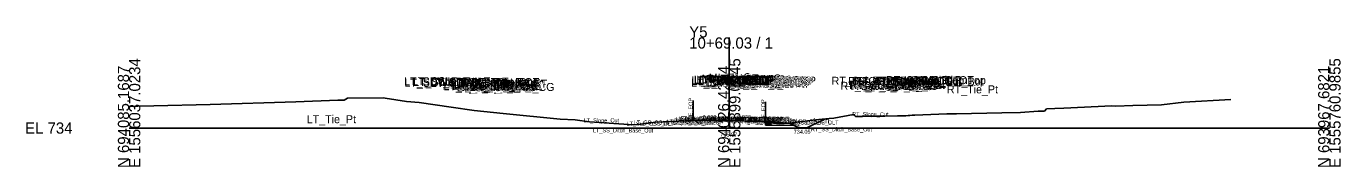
# Model space of a CAD drawing. Extents: x -26 to 4229, y -10 to 9523.
# Drawn here: x -25.7 to 302.8, y 490.3 to 525.5 of the extents above; entities that cross this region are included whole.
import ezdxf

# ---------------------------------------------------------------- set-up
doc = ezdxf.new("R2010")
doc.units = 0
for name, color, linetype in [('Default', 7, 'Continuous'), ('Exist Cross Section Cell', 7, 'Continuous'), ('Exist XS Center Line Elevation Label', 7, 'Continuous'), ('Exist XS Ground Line', 7, 'Continuous'), ('Prop CMT Pvmt Course 1', 7, 'Continuous'), ('Prop CMT Pvmt Course 2', 7, 'Continuous'), ('Prop CMT Pvmt Course 3', 7, 'Continuous'), ('Prop CMT Pvmt Surface', 7, 'Continuous'), ('Prop CMT Pvmt Surface Shoulder', 7, 'Continuous'), ('Prop CMT Pvmt Wedge Surface 1', 7, 'Continuous'), ('Prop CMT Pvmt Wedge Surface 2', 7, 'Continuous'), ('Prop CMT Pvmt Wedge Surface 3', 7, 'Continuous'), ('Prop CMT Shld Paved Course 1', 7, 'Continuous'), ('Prop CMT Shld Paved Course 2', 7, 'Continuous'), ('Prop CMT Shld Paved Course 3', 7, 'Continuous'), ('Prop CMT Slope Grass', 7, 'Continuous'), ('Prop CMT Subgrade Earthwork', 7, 'Continuous'), ('Prop XS Earthwork Shape', 7, 'Continuous'), ('Prop XS Label Text', 7, 'Continuous'), ('Prop XSC Text', 7, 'Continuous'), ('Scratch_Level_1', 7, 'Continuous')]:
    doc.layers.add(name, color=color, linetype=linetype)

msp = doc.modelspace()

# ---------------------------------------------------------------- linework, layer by layer
at = {"layer": 'Exist Cross Section Cell'}
for p, q in [((150, 500), (150, 522.7)), ((0, 500), (150, 500)), ((150, 500), (300, 500))]:
    msp.add_line(p, q, dxfattribs=at)
at = {"layer": 'Exist XS Ground Line'}
msp.add_lwpolyline([(0, 505.41), (2.22, 505.46), (6.16, 505.53), (20.25, 505.91), (41.67, 506.58), (52.17, 507.02), (52.65, 507.01), (53.79, 507), (54.59, 507.5), (63.56, 507.57), (64.04, 507.5), (69.31, 506.67), (72.47, 506.43), (80.52, 505.2), (86.27, 504.37), (93.54, 503.63), (107.74, 502.22), (111.52, 502.03), (115.06, 501.59), (126.06, 500.78), (127.93, 501.01), (131.58, 501.47), (140.95, 501.93), (150, 501.87), (150.54, 501.87), (151.66, 501.83), (158.35, 501.58), (159.09, 501.56), (159.44, 501.53), (159.77, 501.49), (161.09, 501.2), (162.46, 501.08), (165.03, 501.25), (170.25, 501.85), (172.44, 502.13), (174.95, 502.37), (176.18, 502.49), (181.05, 503.4), (181.59, 502.9), (182.81, 502.93), (183.2, 502.95), (188.92, 503.01), (192.05, 503.06), (194.18, 503.09), (194.69, 503.11), (195.18, 503.16), (195.73, 503.19), (196.4, 503.19), (204.41, 503.53), (205.62, 503.55), (206.78, 503.56), (218.18, 503.78), (222.84, 503.92), (227.19, 504.27), (227.92, 504.25), (228.8, 504.27), (229.34, 504.8), (231.35, 504.92), (233.63, 504.96), (245.6, 505.53), (246.63, 505.5), (250.88, 505.68), (258.05, 505.79), (263.61, 506.51), (275.35, 507.12)], dxfattribs=at)
at = {"layer": 'Prop CMT Pvmt Course 1'}
for points in [[(150, 501.89), (159.22, 501.63)], [(159.22, 501.38), (159.09, 501.38)], [(159.22, 501.63), (159.22, 501.38)]]:
    msp.add_lwpolyline(points, dxfattribs=at)
at = {"layer": 'Prop CMT Pvmt Course 2'}
for points in [[(159.09, 501.38), (159.22, 501.38)], [(159.22, 501.13), (159.09, 501.13)], [(159.22, 501.38), (159.22, 501.13)]]:
    msp.add_lwpolyline(points, dxfattribs=at)
at = {"layer": 'Prop CMT Pvmt Course 3'}
for points in [[(159.09, 501.13), (159.22, 501.13)], [(159.22, 500.75), (159.09, 500.76)], [(159.22, 501.13), (159.22, 500.75)]]:
    msp.add_lwpolyline(points, dxfattribs=at)
at = {"layer": 'Prop CMT Pvmt Surface'}
for points in [[(150, 501.89), (140.95, 501.93)], [(150, 501.89), (159.22, 501.63)]]:
    msp.add_lwpolyline(points, dxfattribs=at)
at = {"layer": 'Prop CMT Pvmt Surface Shoulder'}
for points in [[(140.68, 501.9), (140.68, 501.9)], [(159.22, 501.63), (159.22, 501.63)]]:
    msp.add_lwpolyline(points, dxfattribs=at)
at = {"layer": 'Prop CMT Pvmt Wedge Surface 1'}
for points in [[(159.09, 501.38), (159.22, 501.38)], [(159.22, 501.38), (159.22, 501.63)]]:
    msp.add_lwpolyline(points, dxfattribs=at)
at = {"layer": 'Prop CMT Pvmt Wedge Surface 2'}
msp.add_lwpolyline([(159.22, 501.38), (159.22, 501.63)], dxfattribs=at)
at = {"layer": 'Prop CMT Pvmt Wedge Surface 3'}
msp.add_lwpolyline([(159.22, 501.13), (159.22, 501.63)], dxfattribs=at)
at = {"layer": 'Prop CMT Shld Paved Course 1'}
for points in [[(140.68, 501.9), (140.68, 501.9)], [(159.22, 501.63), (159.22, 501.63)], [(159.22, 501.63), (159.47, 501.37)], [(159.22, 501.38), (159.22, 501.63)], [(159.47, 501.37), (159.22, 501.38)]]:
    msp.add_lwpolyline(points, dxfattribs=at)
at = {"layer": 'Prop CMT Shld Paved Course 2'}
for points in [[(159.22, 501.38), (159.47, 501.37), (159.73, 501.12)], [(159.22, 501.13), (159.22, 501.38)], [(159.73, 501.12), (159.22, 501.13)]]:
    msp.add_lwpolyline(points, dxfattribs=at)
at = {"layer": 'Prop CMT Shld Paved Course 3'}
for points in [[(159.22, 501.13), (159.73, 501.12), (160.23, 501.11), (160.61, 500.72)], [(159.22, 500.75), (159.22, 501.13)], [(160.61, 500.72), (159.22, 500.75)]]:
    msp.add_lwpolyline(points, dxfattribs=at)
at = {"layer": 'Prop CMT Slope Grass'}
for p, q in [((165.22, 501.15), (167.41, 500.05)), ((167.41, 500.05), (169.41, 500.05)), ((173.84, 502.26), (169.41, 500.05))]:
    msp.add_line(p, q, dxfattribs=at)
msp.add_lwpolyline([(159.22, 501.63), (165.22, 501.15)], dxfattribs=at)
at = {"layer": 'Prop CMT Subgrade Earthwork'}
for points in [[(159.09, 500.76), (159.09, 501.56)], [(159.09, 500.76), (159.22, 500.75)], [(159.22, 500.75), (160.61, 500.72)], [(160.61, 500.72), (166.29, 500.61)]]:
    msp.add_lwpolyline(points, dxfattribs=at)
at = {"layer": 'Prop XS Earthwork Shape'}
for points in [[(150.54, 501.87), (151.66, 501.83), (158.35, 501.58), (159.09, 501.56), (159.44, 501.53), (159.77, 501.49), (161.09, 501.2), (162.46, 501.08), (164.44, 501.21), (159.22, 501.63), (150, 501.89), (140.95, 501.93), (150, 501.87)], [(160.61, 500.72), (166.29, 500.61), (165.22, 501.15), (164.44, 501.21), (162.46, 501.08), (161.09, 501.2), (159.77, 501.49), (159.44, 501.53), (159.09, 501.56), (159.09, 500.76), (159.22, 500.75)], [(164.44, 501.21), (165.03, 501.25), (170.25, 501.85), (172.44, 502.13), (173.84, 502.26), (169.41, 500.05), (167.41, 500.05), (166.29, 500.61), (165.22, 501.15)]]:
    msp.add_lwpolyline(points, close=True, dxfattribs=at)
at = {"layer": 'Prop XS Label Text'}
for p, q in [((140.95, 506.93), (140.95, 501.93)), ((159.09, 506.56), (159.09, 501.56))]:
    msp.add_line(p, q, dxfattribs=at)

# ---------------------------------------------------------------- texts
at = {"layer": 'Default'}
for s, height, p in [('LT_SDWK_Out_Top', 2, (68.76, 510.71)), ('LT_CSLP_Pnt', 2, (70.7, 510.74)), ('LT_Sub_Trench_Out_DLT', 2, (71.02, 510.54)), ('LT_SDWK_In_Top', 2, (75.39, 510.61)), ('LT_CG_Top_Face', 2, (80.29, 510.5)), ('LT_CG_Top_BOC', 2, (80.81, 510.5)), ('LT_PV2_OEEOP', 2, (140.56, 510.99)), ('LT_PV3_OEEOP', 2, (140.56, 510.74)), ('LT_PV1_OEEOP', 2, (141.12, 511.12)), ('LT_PV2_IEEOP', 2, (141.2, 510.99)), ('LT_PV1_IEEOP', 2, (141.77, 511.12)), ('LT_PV2_PGL1', 2, (142.13, 510.99)), ('LT_PV3_PGL1', 2, (142.13, 510.74)), ('LT_PV2_PGL', 2, (142.46, 510.99)), ('LT_PV1_PGL', 2, (143.03, 511.25)), ('MI_Face In', 2, (143.15, 511.41)), ('MI_Bot In', 2, (144.13, 511.25)), ('MI_Top In', 2, (144.86, 511.66)), ('MI_Crown', 2, (149.07, 511.74)), ('RT_PV2_OEEOP', 2, (150.01, 510.75)), ('RT_PV3_OEEOP', 2, (150.01, 510.5)), ('RT_PV1_OEEOP', 2, (150.58, 510.88)), ('RT_PV2_IEEOP', 2, (150.66, 510.75)), ('MI_Face Out', 2, (151.01, 511.17)), ('MI_Top Out', 2, (151.22, 511.42)), ('RT_PV1_IEEOP', 2, (151.22, 510.88)), ('RT_PV2_PGL1', 2, (151.58, 510.75)), ('RT_PV3_PGL1', 2, (151.58, 510.5)), ('RT_PV2_PGL', 2, (151.92, 510.75)), ('MI_Bot Out', 2, (152.01, 511)), ('RT_PV1_PGL', 2, (152.48, 511)), ('RT_Sub_Trench_Out_DLT', 2, (175.59, 510.83)), ('RT_CG_Top_Face', 2, (179.71, 510.79)), ('RT_CG_Top_BOC', 2, (181.24, 510.79)), ('RT_SDWK_In_Top', 2, (185.81, 510.9)), ('RT_SDWK_In_Bot', 2, (185.84, 510.57)), ('RT_SDWK_Out_Top', 2, (189.19, 511)), ('RT_SDWK_Out_Bot', 2, (189.22, 510.67)), ('RT_Shld_O', 2, (195.54, 510.99)), ('CSLP_Pnt', 2, (197.87, 511.03)), ('LT_SDWK_Out_Bot', 2, (68.79, 510.38)), ('LT_SDWK_In_Bot', 2, (75.42, 510.28)), ('LT_CG1_Shelf_Out', 2, (78.58, 509.48)), ('LT_CG_Bot_BOC', 2, (80.84, 509.49)), ('LT_CG_Top_Gut', 2, (81.26, 510)), ('LT_Sub_OEOP', 2, (81.88, 509.22)), ('LT_Sub_OEOT_CG', 2, (82.4, 509.29)), ('LT_CG_Bot_IE', 2, (84.94, 509.54)), ('LT_Sub_OEOT', 2, (85.11, 509.25)), ('LT_PV2_OEOT', 2, (85.2, 509.87)), ('LT_PV3_OEOT', 2, (85.2, 509.62)), ('LT_PV1_OEOT', 2, (85.77, 510.12)), ('LT_Sub_OEEOP', 2, (140.46, 510.37)), ('LT_PV4_PGL', 2, (142.46, 510.37)), ('RT_Sub_OEEOP', 2, (149.92, 510.13)), ('RT_PV4_PGL', 2, (151.92, 510.13)), ('RT_Sub_OEOT_CG', 2, (177.82, 509.58)), ('RT_CG1_Shelf_Out', 2, (180, 509.77)), ('RT_CG_Bot_IE', 2, (180.37, 509.83)), ('RT_Sub_OEOT', 2, (180.53, 509.53)), ('RT_PV2_OEOT', 2, (180.63, 510.16)), ('RT_PV3_OEOT', 2, (180.63, 509.91)), ('RT_CG_Top_Gut', 2, (180.69, 510.29)), ('RT_PV1_OEOT', 2, (181.19, 510.41)), ('RT_CG_Bot_BOC', 2, (181.27, 509.78)), ('RT_Sub_OEOP', 2, (183.82, 509.51)), ('RT_Tie_Pt', 2, (204.41, 508.69)), ('LT_Tie_Pt', 2, (44.39, 501.22)), ('-', 0.0001, (0, 500)), ('-', 0.0001, (0, 500)), ('-', 0.0001, (0, 500)), ('-', 0.0001, (0, 500)), ('-', 0.0001, (0, 500)), ('-', 0.0001, (0, 500)), ('-', 0.0001, (0, 500)), ('-', 0.0001, (0, 500)), ('-', 0.0001, (0, 500)), ('-', 0.0001, (0, 500))]:
    msp.add_text(s, height=height, dxfattribs=at).set_placement(p)
at = {"layer": 'Exist Cross Section Cell'}
for s, p in [('Y5', (140, 522.7)), ('10+69.03 / 1', (140, 519.9)), ('EL 734', (-26, 498.6))]:
    msp.add_text(s, height=2.8, dxfattribs=at).set_placement(p)
for s, p in [('E 1556037.0234', (2.8, 490)), ('E 1555899.0045', (152.8, 490)), ('E 1555760.9855', (302.8, 490)), ('N 694085.1687', (0, 490)), ('N 694026.4254', (150, 490)), ('N 693967.6821', (300, 490))]:
    msp.add_text(s, height=2.8, rotation=90, dxfattribs=at).set_placement(p)
at = {"layer": 'Exist XS Center Line Elevation Label'}
msp.add_text('735.87', height=1, dxfattribs=at).set_placement((147.77, 497.87))
at = {"layer": 'Prop XS Label Text'}
for p in [(140.85, 502.94), (158.99, 502.58)]:
    msp.add_text('E. EOP', height=1, rotation=90, dxfattribs=at).set_placement(p)
at = {"layer": 'Prop XSC Text'}
for s, rotation, p in [('0.002', 359.9083, (143.36, 502.23)), ('0.028', 358.3732, (151.99, 502.31)), ('2:1', 333.4349, (165.83, 501.2)), ('2:1', 26.5651, (170.31, 500.91))]:
    msp.add_text(s, height=1, rotation=rotation, dxfattribs=at).set_placement(p)
msp.add_text('734.05', height=1, dxfattribs=at).set_placement((166.11, 498.57))
at = {"layer": 'Scratch_Level_1'}
for s, p in [('LT_PV1_OEOT', (136.55, 501.71)), ('LT_PS1_OEOP', (136.59, 501.71)), ('LT_PV_OEEOP_EG', (137.3, 501.92)), ('LT_Sub Tie Out', (137.86, 501.92)), ('RT_PV_IEEOP_EG', (144.92, 501.88)), ('LT_PV_IEEOP_EG', (144.98, 501.88)), ('RT_PV1_IEEOP', (145.83, 501.77)), ('LT_PV1_IEEOP', (145.89, 501.77)), ('PV2_PGL', (147.35, 501.65)), ('PV1_PGL', (147.47, 501.89)), ('RT_Sub Tie Out', (152.31, 501.64)), ('RT_PV2_OEEOP', (152.55, 501.72)), ('RT_PV1_OEEOP', (152.67, 501.85)), ('RT_PV2_OEOT', (154.91, 501.74)), ('RT_PV1_OEOT', (155.03, 501.99)), ('RT_PS1_OEOP', (155.07, 501.99)), ('RT_PS2_OEOP', (155.2, 501.74)), ('RT_Slope_Cut', (180.74, 502.98)), ('LT_Slope_Cut', (113.61, 501.45)), ('LT_SS_Ditch_Base_Out', (115.94, 498.92)), ('LT_Sub_OSS_DLT', (124.33, 500.62)), ('LT_GS_OS_CTL', (126.15, 500.91)), ('LT_Sub_Trench_Out', (133.4, 500.81)), ('LT_PS3_Shelf_Out', (134.33, 501.19)), ('LT_PS3_OEOP', (135.96, 501.2)), ('LT_PS2_OEOP', (136.21, 501.46)), ('LT_PV2_OEOT', (136.43, 501.46)), ('LT_PV3_OEOT', (136.43, 501.21)), ('LT_Sub_OEOT', (136.45, 500.84)), ('LT_PV2_OEEOP', (138.1, 501.5)), ('LT_PV3_OEEOP', (138.1, 501.25)), ('LT_Sub_OEEOP', (138.12, 500.88)), ('LT_PV1_OEEOP', (138.22, 501.63)), ('RT_PV2_IEEOP', (145.71, 501.65)), ('RT_PV3_IEEOP', (145.71, 501.4)), ('LT_PV2_IEEOP', (145.77, 501.65)), ('LT_PV3_IEEOP', (145.77, 501.4)), ('RT_PV_OEEOP_EG', (151.76, 501.64)), ('RT_PV3_OEEOP', (152.55, 501.47)), ('RT_Sub_OEEOP', (152.58, 501.1)), ('RT_Sub_Trench_Out', (154.66, 501.09)), ('RT_PS3_Shelf_Out', (154.83, 501.47)), ('RT_PV3_OEOT', (154.91, 501.49)), ('RT_Sub_OEOT', (154.93, 501.12)), ('RT_PS3_OEOP', (155.46, 501.48)), ('RT_GS_OS_CTL', (164.62, 501.19)), ('RT_Sub_OSS_DLT', (165.2, 500.89)), ('RT_SS_Ditch_Base_Out', (170.42, 499.2))]:
    msp.add_text(s, height=1, rotation=359.8763, dxfattribs=at).set_placement(p)

doc.saveas('drawing.dxf')
